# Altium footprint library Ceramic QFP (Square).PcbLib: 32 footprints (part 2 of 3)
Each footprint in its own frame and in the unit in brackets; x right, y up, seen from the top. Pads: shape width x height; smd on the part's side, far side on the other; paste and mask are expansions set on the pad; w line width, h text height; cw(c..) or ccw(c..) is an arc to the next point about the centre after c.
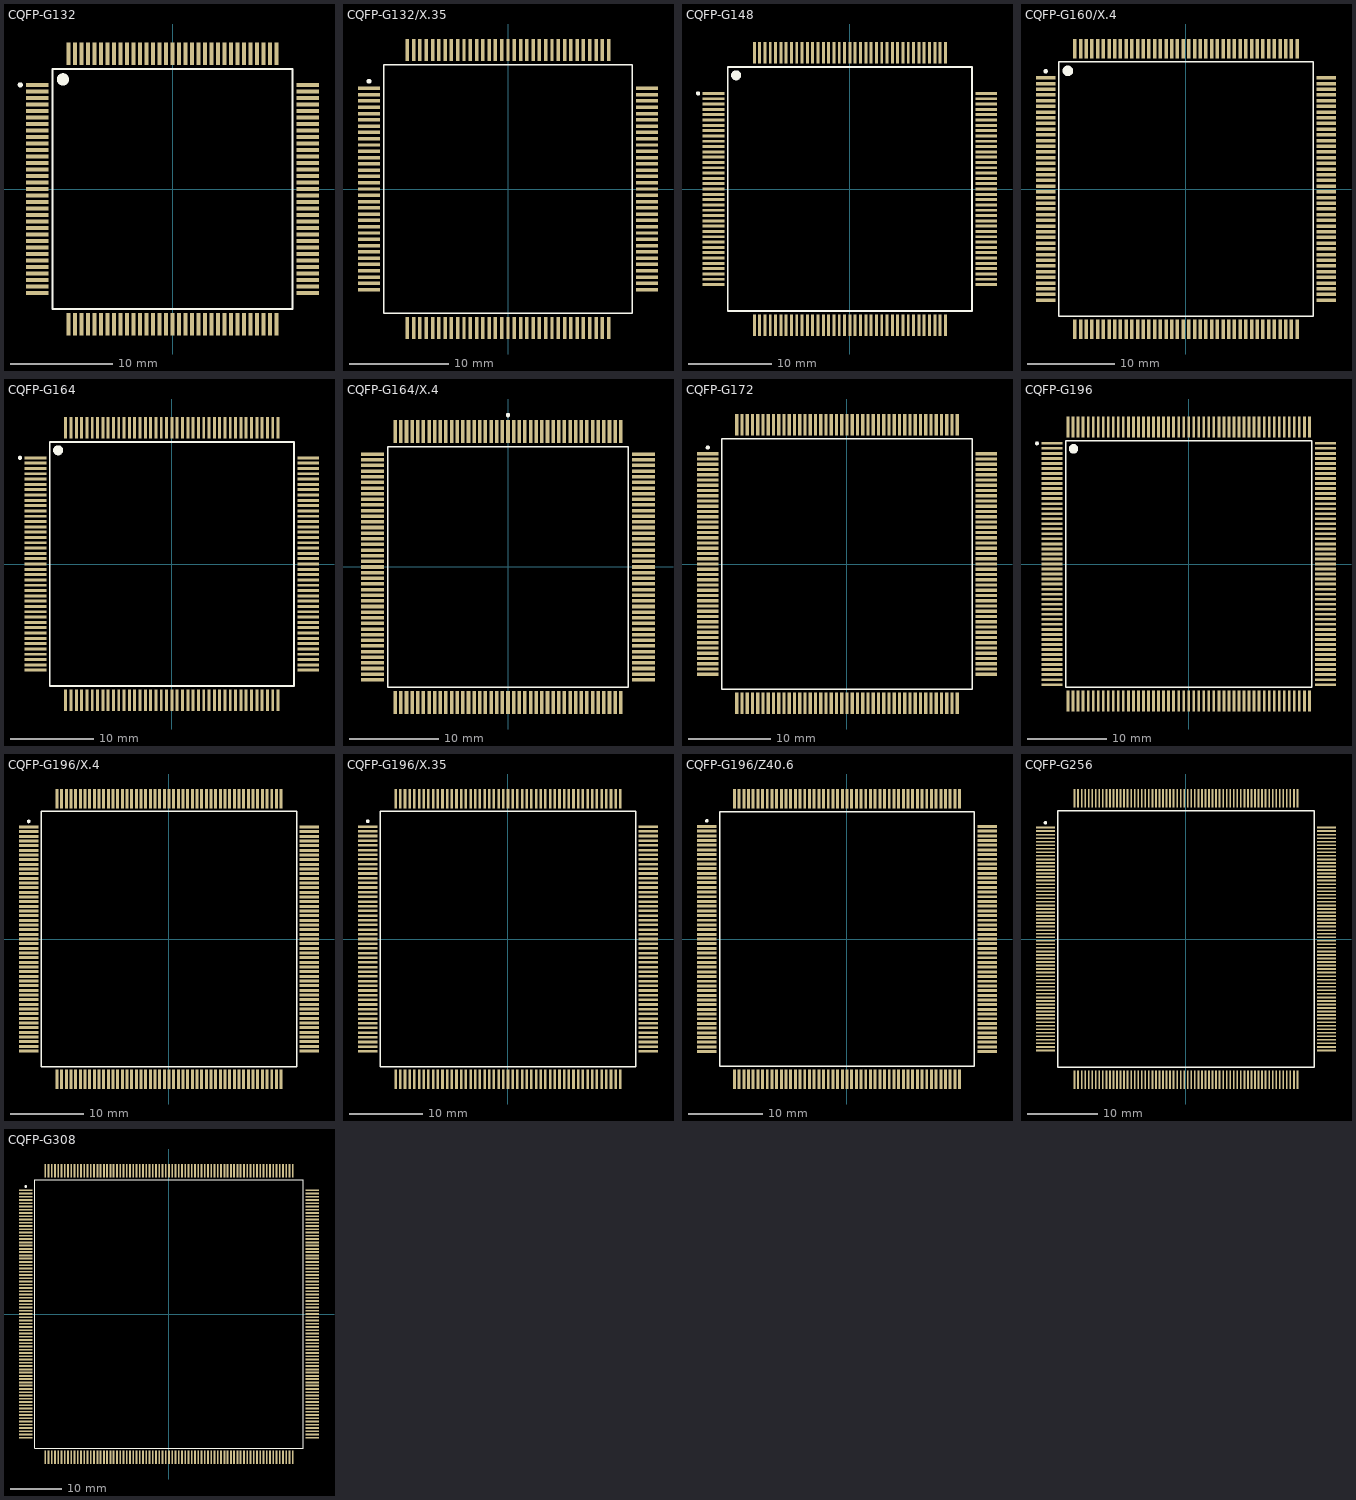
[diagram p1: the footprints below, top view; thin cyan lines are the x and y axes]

## CQFP-G132 [mm]
pads (132):
  rect 2.2x0.4 smd: 1(-13.2,10.16) 2(-13.2,9.525) 3(-13.2,8.89) 4(-13.2,8.255) 5(-13.2,7.62) 6(-13.2,6.985) 7(-13.2,6.35) 8(-13.2,5.715) 9(-13.2,5.08) 10(-13.2,4.445) 11(-13.2,3.81) 12(-13.2,3.175) 13(-13.2,2.54) 14(-13.2,1.905) 15(-13.2,1.27) 16(-13.2,0.635) 17(-13.2,0) 18(-13.2,-0.635) 19(-13.2,-1.27) 20(-13.2,-1.905) 21(-13.2,-2.54) 22(-13.2,-3.175) 23(-13.2,-3.81) 24(-13.2,-4.445) 25(-13.2,-5.08) 26(-13.2,-5.715) 27(-13.2,-6.35) 28(-13.2,-6.985) 29(-13.2,-7.62) 30(-13.2,-8.255) 31(-13.2,-8.89) 32(-13.2,-9.525) 33(-13.2,-10.16) 67(13.2,-10.16) 68(13.2,-9.525) 69(13.2,-8.89) 70(13.2,-8.255) 71(13.2,-7.62) 72(13.2,-6.985) 73(13.2,-6.35) 74(13.2,-5.715) 75(13.2,-5.08) 76(13.2,-4.445) 77(13.2,-3.81) 78(13.2,-3.175) 79(13.2,-2.54) 80(13.2,-1.905) 81(13.2,-1.27) 82(13.2,-0.635) 83(13.2,0) 84(13.2,0.635) 85(13.2,1.27) 86(13.2,1.905) 87(13.2,2.54) 88(13.2,3.175) 89(13.2,3.81) 90(13.2,4.445) 91(13.2,5.08) 92(13.2,5.715) 93(13.2,6.35) 94(13.2,6.985) 95(13.2,7.62) 96(13.2,8.255) 97(13.2,8.89) 98(13.2,9.525) 99(13.2,10.16)
  rect 0.4x2.2 smd: 34(-10.16,-13.2) 35(-9.525,-13.2) 36(-8.89,-13.2) 37(-8.255,-13.2) 38(-7.62,-13.2) 39(-6.985,-13.2) 40(-6.35,-13.2) 41(-5.715,-13.2) 42(-5.08,-13.2) 43(-4.445,-13.2) 44(-3.81,-13.2) 45(-3.175,-13.2) 46(-2.54,-13.2) 47(-1.905,-13.2) 48(-1.27,-13.2) 49(-0.635,-13.2) 50(0,-13.2) 51(0.635,-13.2) 52(1.27,-13.2) 53(1.905,-13.2) 54(2.54,-13.2) 55(3.175,-13.2) 56(3.81,-13.2) 57(4.445,-13.2) 58(5.08,-13.2) 59(5.715,-13.2) 60(6.35,-13.2) 61(6.985,-13.2) 62(7.62,-13.2) 63(8.255,-13.2) 64(8.89,-13.2) 65(9.525,-13.2) 66(10.16,-13.2) 100(10.16,13.2) 101(9.525,13.2) 102(8.89,13.2) 103(8.255,13.2) 104(7.62,13.2) 105(6.985,13.2) 106(6.35,13.2) 107(5.715,13.2) 108(5.08,13.2) 109(4.445,13.2) 110(3.81,13.2) 111(3.175,13.2) 112(2.54,13.2) 113(1.905,13.2) 114(1.27,13.2) 115(0.635,13.2) 116(0,13.2) 117(-0.635,13.2) 118(-1.27,13.2) 119(-1.905,13.2) 120(-2.54,13.2) 121(-3.175,13.2) 122(-3.81,13.2) 123(-4.445,13.2) 124(-5.08,13.2) 125(-5.715,13.2) 126(-6.35,13.2) 127(-6.985,13.2) 128(-7.62,13.2) 129(-8.255,13.2) 130(-8.89,13.2) 131(-9.525,13.2) 132(-10.16,13.2)
Top Overlay:
  circle w0.6: c-10.7,10.7 r0.3
  circle w0.25: c-14.86,10.16 r0.125
  lines w0.2: -11.7,-11.7 -11.7,11.7 11.7,11.7 11.7,-11.7 -11.7,-11.7

## CQFP-G132/X.35 [mm]
pads (132):
  rect 2.2x0.35 smd: 1(-14.05,10.16) 2(-14.05,9.525) 3(-14.05,8.89) 4(-14.05,8.255) 5(-14.05,7.62) 6(-14.05,6.985) 7(-14.05,6.35) 8(-14.05,5.715) 9(-14.05,5.08) 10(-14.05,4.445) 11(-14.05,3.81) 12(-14.05,3.175) 13(-14.05,2.54) 14(-14.05,1.905) 15(-14.05,1.27) 16(-14.05,0.635) 17(-14.05,0) 18(-14.05,-0.635) 19(-14.05,-1.27) 20(-14.05,-1.905) 21(-14.05,-2.54) 22(-14.05,-3.175) 23(-14.05,-3.81) 24(-14.05,-4.445) 25(-14.05,-5.08) 26(-14.05,-5.715) 27(-14.05,-6.35) 28(-14.05,-6.985) 29(-14.05,-7.62) 30(-14.05,-8.255) 31(-14.05,-8.89) 32(-14.05,-9.525) 33(-14.05,-10.16) 67(14.05,-10.16) 68(14.05,-9.525) 69(14.05,-8.89) 70(14.05,-8.255) 71(14.05,-7.62) 72(14.05,-6.985) 73(14.05,-6.35) 74(14.05,-5.715) 75(14.05,-5.08) 76(14.05,-4.445) 77(14.05,-3.81) 78(14.05,-3.175) 79(14.05,-2.54) 80(14.05,-1.905) 81(14.05,-1.27) 82(14.05,-0.635) 83(14.05,0) 84(14.05,0.635) 85(14.05,1.27) 86(14.05,1.905) 87(14.05,2.54) 88(14.05,3.175) 89(14.05,3.81) 90(14.05,4.445) 91(14.05,5.08) 92(14.05,5.715) 93(14.05,6.35) 94(14.05,6.985) 95(14.05,7.62) 96(14.05,8.255) 97(14.05,8.89) 98(14.05,9.525) 99(14.05,10.16)
  rect 0.35x2.2 smd: 34(-10.16,-14.05) 35(-9.525,-14.05) 36(-8.89,-14.05) 37(-8.255,-14.05) 38(-7.62,-14.05) 39(-6.985,-14.05) 40(-6.35,-14.05) 41(-5.715,-14.05) 42(-5.08,-14.05) 43(-4.445,-14.05) 44(-3.81,-14.05) 45(-3.175,-14.05) 46(-2.54,-14.05) 47(-1.905,-14.05) 48(-1.27,-14.05) 49(-0.635,-14.05) 50(0,-14.05) 51(0.635,-14.05) 52(1.27,-14.05) 53(1.905,-14.05) 54(2.54,-14.05) 55(3.175,-14.05) 56(3.81,-14.05) 57(4.445,-14.05) 58(5.08,-14.05) 59(5.715,-14.05) 60(6.35,-14.05) 61(6.985,-14.05) 62(7.62,-14.05) 63(8.255,-14.05) 64(8.89,-14.05) 65(9.525,-14.05) 66(10.16,-14.05) 100(10.16,14.05) 101(9.525,14.05) 102(8.89,14.05) 103(8.255,14.05) 104(7.62,14.05) 105(6.985,14.05) 106(6.35,14.05) 107(5.715,14.05) 108(5.08,14.05) 109(4.445,14.05) 110(3.81,14.05) 111(3.175,14.05) 112(2.54,14.05) 113(1.905,14.05) 114(1.27,14.05) 115(0.635,14.05) 116(0,14.05) 117(-0.635,14.05) 118(-1.27,14.05) 119(-1.905,14.05) 120(-2.54,14.05) 121(-3.175,14.05) 122(-3.81,14.05) 123(-4.445,14.05) 124(-5.08,14.05) 125(-5.715,14.05) 126(-6.35,14.05) 127(-6.985,14.05) 128(-7.62,14.05) 129(-8.255,14.05) 130(-8.89,14.05) 131(-9.525,14.05) 132(-10.16,14.05)
Top Overlay:
  circle w0.25: c-14.05,10.885 r0.125
  lines w0.2: -12.55,-12.55 12.55,-12.55 12.55,12.55 -12.55,12.55 -12.55,-12.55

## CQFP-G148 [mm]
pads (148):
  rect 2.6x0.35 smd: 1(-16.3,11.43) 2(-16.3,10.795) 3(-16.3,10.16) 4(-16.3,9.525) 5(-16.3,8.89) 6(-16.3,8.255) 7(-16.3,7.62) 8(-16.3,6.985) 9(-16.3,6.35) 10(-16.3,5.715) 11(-16.3,5.08) 12(-16.3,4.445) 13(-16.3,3.81) 14(-16.3,3.175) 15(-16.3,2.54) 16(-16.3,1.905) 17(-16.3,1.27) 18(-16.3,0.635) 19(-16.3,0) 20(-16.3,-0.635) 21(-16.3,-1.27) 22(-16.3,-1.905) 23(-16.3,-2.54) 24(-16.3,-3.175) 25(-16.3,-3.81) 26(-16.3,-4.445) 27(-16.3,-5.08) 28(-16.3,-5.715) 29(-16.3,-6.35) 30(-16.3,-6.985) 31(-16.3,-7.62) 32(-16.3,-8.255) 33(-16.3,-8.89) 34(-16.3,-9.525) 35(-16.3,-10.16) 36(-16.3,-10.795) 37(-16.3,-11.43) 75(16.3,-11.43) 76(16.3,-10.795) 77(16.3,-10.16) 78(16.3,-9.525) 79(16.3,-8.89) 80(16.3,-8.255) 81(16.3,-7.62) 82(16.3,-6.985) 83(16.3,-6.35) 84(16.3,-5.715) 85(16.3,-5.08) 86(16.3,-4.445) 87(16.3,-3.81) 88(16.3,-3.175) 89(16.3,-2.54) 90(16.3,-1.905) 91(16.3,-1.27) 92(16.3,-0.635) 93(16.3,0) 94(16.3,0.635) 95(16.3,1.27) 96(16.3,1.905) 97(16.3,2.54) 98(16.3,3.175) 99(16.3,3.81) 100(16.3,4.445) 101(16.3,5.08) 102(16.3,5.715) 103(16.3,6.35) 104(16.3,6.985) 105(16.3,7.62) 106(16.3,8.255) 107(16.3,8.89) 108(16.3,9.525) 109(16.3,10.16) 110(16.3,10.795) 111(16.3,11.43)
  rect 0.35x2.6 smd: 38(-11.43,-16.3) 39(-10.795,-16.3) 40(-10.16,-16.3) 41(-9.525,-16.3) 42(-8.89,-16.3) 43(-8.255,-16.3) 44(-7.62,-16.3) 45(-6.985,-16.3) 46(-6.35,-16.3) 47(-5.715,-16.3) 48(-5.08,-16.3) 49(-4.445,-16.3) 50(-3.81,-16.3) 51(-3.175,-16.3) 52(-2.54,-16.3) 53(-1.905,-16.3) 54(-1.27,-16.3) 55(-0.635,-16.3) 56(0,-16.3) 57(0.635,-16.3) 58(1.27,-16.3) 59(1.905,-16.3) 60(2.54,-16.3) 61(3.175,-16.3) 62(3.81,-16.3) 63(4.445,-16.3) 64(5.08,-16.3) 65(5.715,-16.3) 66(6.35,-16.3) 67(6.985,-16.3) 68(7.62,-16.3) 69(8.255,-16.3) 70(8.89,-16.3) 71(9.525,-16.3) 72(10.16,-16.3) 73(10.795,-16.3) 74(11.43,-16.3) 112(11.43,16.3) 113(10.795,16.3) 114(10.16,16.3) 115(9.525,16.3) 116(8.89,16.3) 117(8.255,16.3) 118(7.62,16.3) 119(6.985,16.3) 120(6.35,16.3) 121(5.715,16.3) 122(5.08,16.3) 123(4.445,16.3) 124(3.81,16.3) 125(3.175,16.3) 126(2.54,16.3) 127(1.905,16.3) 128(1.27,16.3) 129(0.635,16.3) 130(0,16.3) 131(-0.635,16.3) 132(-1.27,16.3) 133(-1.905,16.3) 134(-2.54,16.3) 135(-3.175,16.3) 136(-3.81,16.3) 137(-4.445,16.3) 138(-5.08,16.3) 139(-5.715,16.3) 140(-6.35,16.3) 141(-6.985,16.3) 142(-7.62,16.3) 143(-8.255,16.3) 144(-8.89,16.3) 145(-9.525,16.3) 146(-10.16,16.3) 147(-10.795,16.3) 148(-11.43,16.3)
Top Overlay:
  circle w0.6: c-13.6,13.6 r0.3
  circle w0.25: c-18.16,11.43 r0.125
  lines w0.2: -14.6,-14.6 -14.6,14.6 14.6,14.6 14.6,-14.6 -14.6,-14.6

## CQFP-G160/X.4 [mm]
pads (160):
  rect 2.2x0.4 smd: 1(-16,12.675) 2(-16,12.025) 3(-16,11.375) 4(-16,10.725) 5(-16,10.075) 6(-16,9.425) 7(-16,8.775) 8(-16,8.125) 9(-16,7.475) 10(-16,6.825) 11(-16,6.175) 12(-16,5.525) 13(-16,4.875) 14(-16,4.225) 15(-16,3.575) 16(-16,2.925) 17(-16,2.275) 18(-16,1.625) 19(-16,0.975) 20(-16,0.325) 21(-16,-0.325) 22(-16,-0.975) 23(-16,-1.625) 24(-16,-2.275) 25(-16,-2.925) 26(-16,-3.575) 27(-16,-4.225) 28(-16,-4.875) 29(-16,-5.525) 30(-16,-6.175) 31(-16,-6.825) 32(-16,-7.475) 33(-16,-8.125) 34(-16,-8.775) 35(-16,-9.425) 36(-16,-10.075) 37(-16,-10.725) 38(-16,-11.375) 39(-16,-12.025) 40(-16,-12.675) 81(16,-12.675) 82(16,-12.025) 83(16,-11.375) 84(16,-10.725) 85(16,-10.075) 86(16,-9.425) 87(16,-8.775) 88(16,-8.125) 89(16,-7.475) 90(16,-6.825) 91(16,-6.175) 92(16,-5.525) 93(16,-4.875) 94(16,-4.225) 95(16,-3.575) 96(16,-2.925) 97(16,-2.275) 98(16,-1.625) 99(16,-0.975) 100(16,-0.325) 101(16,0.325) 102(16,0.975) 103(16,1.625) 104(16,2.275) 105(16,2.925) 106(16,3.575) 107(16,4.225) 108(16,4.875) 109(16,5.525) 110(16,6.175) 111(16,6.825) 112(16,7.475) 113(16,8.125) 114(16,8.775) 115(16,9.425) 116(16,10.075) 117(16,10.725) 118(16,11.375) 119(16,12.025) 120(16,12.675)
  rect 0.4x2.2 smd: 41(-12.675,-16) 42(-12.025,-16) 43(-11.375,-16) 44(-10.725,-16) 45(-10.075,-16) 46(-9.425,-16) 47(-8.775,-16) 48(-8.125,-16) 49(-7.475,-16) 50(-6.825,-16) 51(-6.175,-16) 52(-5.525,-16) 53(-4.875,-16) 54(-4.225,-16) 55(-3.575,-16) 56(-2.925,-16) 57(-2.275,-16) 58(-1.625,-16) 59(-0.975,-16) 60(-0.325,-16) 61(0.325,-16) 62(0.975,-16) 63(1.625,-16) 64(2.275,-16) 65(2.925,-16) 66(3.575,-16) 67(4.225,-16) 68(4.875,-16) 69(5.525,-16) 70(6.175,-16) 71(6.825,-16) 72(7.475,-16) 73(8.125,-16) 74(8.775,-16) 75(9.425,-16) 76(10.075,-16) 77(10.725,-16) 78(11.375,-16) 79(12.025,-16) 80(12.675,-16) 121(12.675,16) 122(12.025,16) 123(11.375,16) 124(10.725,16) 125(10.075,16) 126(9.425,16) 127(8.775,16) 128(8.125,16) 129(7.475,16) 130(6.825,16) 131(6.175,16) 132(5.525,16) 133(4.875,16) 134(4.225,16) 135(3.575,16) 136(2.925,16) 137(2.275,16) 138(1.625,16) 139(0.975,16) 140(0.325,16) 141(-0.325,16) 142(-0.975,16) 143(-1.625,16) 144(-2.275,16) 145(-2.925,16) 146(-3.575,16) 147(-4.225,16) 148(-4.875,16) 149(-5.525,16) 150(-6.175,16) 151(-6.825,16) 152(-7.475,16) 153(-8.125,16) 154(-8.775,16) 155(-9.425,16) 156(-10.075,16) 157(-10.725,16) 158(-11.375,16) 159(-12.025,16) 160(-12.675,16)
Top Overlay:
  circle w0.6: c-13.47,13.47 r0.3
  circle w0.25: c-16,13.425 r0.125
  lines w0.2: -14.5,-14.5 -14.5,14.5 14.5,14.5 14.5,-14.5 -14.5,-14.5

## CQFP-G164 [mm]
pads (164):
  rect 2.6x0.35 smd: 1(-16.3,12.7) 2(-16.3,12.065) 3(-16.3,11.43) 4(-16.3,10.795) 5(-16.3,10.16) 6(-16.3,9.525) 7(-16.3,8.89) 8(-16.3,8.255) 9(-16.3,7.62) 10(-16.3,6.985) 11(-16.3,6.35) 12(-16.3,5.715) 13(-16.3,5.08) 14(-16.3,4.445) 15(-16.3,3.81) 16(-16.3,3.175) 17(-16.3,2.54) 18(-16.3,1.905) 19(-16.3,1.27) 20(-16.3,0.635) 21(-16.3,0) 22(-16.3,-0.635) 23(-16.3,-1.27) 24(-16.3,-1.905) 25(-16.3,-2.54) 26(-16.3,-3.175) 27(-16.3,-3.81) 28(-16.3,-4.445) 29(-16.3,-5.08) 30(-16.3,-5.715) 31(-16.3,-6.35) 32(-16.3,-6.985) 33(-16.3,-7.62) 34(-16.3,-8.255) 35(-16.3,-8.89) 36(-16.3,-9.525) 37(-16.3,-10.16) 38(-16.3,-10.795) 39(-16.3,-11.43) 40(-16.3,-12.065) 41(-16.3,-12.7) 83(16.3,-12.7) 84(16.3,-12.065) 85(16.3,-11.43) 86(16.3,-10.795) 87(16.3,-10.16) 88(16.3,-9.525) 89(16.3,-8.89) 90(16.3,-8.255) 91(16.3,-7.62) 92(16.3,-6.985) 93(16.3,-6.35) 94(16.3,-5.715) 95(16.3,-5.08) 96(16.3,-4.445) 97(16.3,-3.81) 98(16.3,-3.175) 99(16.3,-2.54) 100(16.3,-1.905) 101(16.3,-1.27) 102(16.3,-0.635) 103(16.3,0) 104(16.3,0.635) 105(16.3,1.27) 106(16.3,1.905) 107(16.3,2.54) 108(16.3,3.175) 109(16.3,3.81) 110(16.3,4.445) 111(16.3,5.08) 112(16.3,5.715) 113(16.3,6.35) 114(16.3,6.985) 115(16.3,7.62) 116(16.3,8.255) 117(16.3,8.89) 118(16.3,9.525) 119(16.3,10.16) 120(16.3,10.795) 121(16.3,11.43) 122(16.3,12.065) 123(16.3,12.7)
  rect 0.35x2.6 smd: 42(-12.7,-16.3) 43(-12.065,-16.3) 44(-11.43,-16.3) 45(-10.795,-16.3) 46(-10.16,-16.3) 47(-9.525,-16.3) 48(-8.89,-16.3) 49(-8.255,-16.3) 50(-7.62,-16.3) 51(-6.985,-16.3) 52(-6.35,-16.3) 53(-5.715,-16.3) 54(-5.08,-16.3) 55(-4.445,-16.3) 56(-3.81,-16.3) 57(-3.175,-16.3) 58(-2.54,-16.3) 59(-1.905,-16.3) 60(-1.27,-16.3) 61(-0.635,-16.3) 62(0,-16.3) 63(0.635,-16.3) 64(1.27,-16.3) 65(1.905,-16.3) 66(2.54,-16.3) 67(3.175,-16.3) 68(3.81,-16.3) 69(4.445,-16.3) 70(5.08,-16.3) 71(5.715,-16.3) 72(6.35,-16.3) 73(6.985,-16.3) 74(7.62,-16.3) 75(8.255,-16.3) 76(8.89,-16.3) 77(9.525,-16.3) 78(10.16,-16.3) 79(10.795,-16.3) 80(11.43,-16.3) 81(12.065,-16.3) 82(12.7,-16.3) 124(12.7,16.3) 125(12.065,16.3) 126(11.43,16.3) 127(10.795,16.3) 128(10.16,16.3) 129(9.525,16.3) 130(8.89,16.3) 131(8.255,16.3) 132(7.62,16.3) 133(6.985,16.3) 134(6.35,16.3) 135(5.715,16.3) 136(5.08,16.3) 137(4.445,16.3) 138(3.81,16.3) 139(3.175,16.3) 140(2.54,16.3) 141(1.905,16.3) 142(1.27,16.3) 143(0.635,16.3) 144(0,16.3) 145(-0.635,16.3) 146(-1.27,16.3) 147(-1.905,16.3) 148(-2.54,16.3) 149(-3.175,16.3) 150(-3.81,16.3) 151(-4.445,16.3) 152(-5.08,16.3) 153(-5.715,16.3) 154(-6.35,16.3) 155(-6.985,16.3) 156(-7.62,16.3) 157(-8.255,16.3) 158(-8.89,16.3) 159(-9.525,16.3) 160(-10.16,16.3) 161(-10.795,16.3) 162(-11.43,16.3) 163(-12.065,16.3) 164(-12.7,16.3)
Top Overlay:
  circle w0.25: c-18.16,12.7 r0.125
  circle w0.6: c-13.6,13.6 r0.3
  lines w0.2: -14.6,-14.6 14.6,-14.6 14.6,14.6 -14.6,14.6 -14.6,-14.6

## CQFP-G164/X.4 [mm]
pads (164):
  rect 0.4x2.6 smd: 1(0,15.25) 2(-0.635,15.25) 3(-1.27,15.25) 4(-1.905,15.25) 5(-2.54,15.25) 6(-3.175,15.25) 7(-3.81,15.25) 8(-4.445,15.25) 9(-5.08,15.25) 10(-5.715,15.25) 11(-6.35,15.25) 12(-6.985,15.25) 13(-7.62,15.25) 14(-8.255,15.25) 15(-8.89,15.25) 16(-9.525,15.25) 17(-10.16,15.25) 18(-10.795,15.25) 19(-11.43,15.25) 20(-12.065,15.25) 21(-12.7,15.25) 63(-12.7,-15.25) 64(-12.065,-15.25) 65(-11.43,-15.25) 66(-10.795,-15.25) 67(-10.16,-15.25) 68(-9.525,-15.25) 69(-8.89,-15.25) 70(-8.255,-15.25) 71(-7.62,-15.25) 72(-6.985,-15.25) 73(-6.35,-15.25) 74(-5.715,-15.25) 75(-5.08,-15.25) 76(-4.445,-15.25) 77(-3.81,-15.25) 78(-3.175,-15.25) 79(-2.54,-15.25) 80(-1.905,-15.25) 81(-1.27,-15.25) 82(-0.635,-15.25) 83(0,-15.25) 84(0.635,-15.25) 85(1.27,-15.25) 86(1.905,-15.25) 87(2.54,-15.25) 88(3.175,-15.25) 89(3.81,-15.25) 90(4.445,-15.25) 91(5.08,-15.25) 92(5.715,-15.25) 93(6.35,-15.25) 94(6.985,-15.25) 95(7.62,-15.25) 96(8.255,-15.25) 97(8.89,-15.25) 98(9.525,-15.25) 99(10.16,-15.25) 100(10.795,-15.25) 101(11.43,-15.25) 102(12.065,-15.25) 103(12.7,-15.25) 145(12.7,15.25) 146(12.065,15.25) 147(11.43,15.25) 148(10.795,15.25) 149(10.16,15.25) 150(9.525,15.25) 151(8.89,15.25) 152(8.255,15.25) 153(7.62,15.25) 154(6.985,15.25) 155(6.35,15.25) 156(5.715,15.25) 157(5.08,15.25) 158(4.445,15.25) 159(3.81,15.25) 160(3.175,15.25) 161(2.54,15.25) 162(1.905,15.25) 163(1.27,15.25) 164(0.635,15.25)
  rect 2.6x0.4 smd: 22(-15.25,12.7) 23(-15.25,12.065) 24(-15.25,11.43) 25(-15.25,10.795) 26(-15.25,10.16) 27(-15.25,9.525) 28(-15.25,8.89) 29(-15.25,8.255) 30(-15.25,7.62) 31(-15.25,6.985) 32(-15.25,6.35) 33(-15.25,5.715) 34(-15.25,5.08) 35(-15.25,4.445) 36(-15.25,3.81) 37(-15.25,3.175) 38(-15.25,2.54) 39(-15.25,1.905) 40(-15.25,1.27) 41(-15.25,0.635) 42(-15.25,0) 43(-15.25,-0.635) 44(-15.25,-1.27) 45(-15.25,-1.905) 46(-15.25,-2.54) 47(-15.25,-3.175) 48(-15.25,-3.81) 49(-15.25,-4.445) 50(-15.25,-5.08) 51(-15.25,-5.715) 52(-15.25,-6.35) 53(-15.25,-6.985) 54(-15.25,-7.62) 55(-15.25,-8.255) 56(-15.25,-8.89) 57(-15.25,-9.525) 58(-15.25,-10.16) 59(-15.25,-10.795) 60(-15.25,-11.43) 61(-15.25,-12.065) 62(-15.25,-12.7) 104(15.25,-12.7) 105(15.25,-12.065) 106(15.25,-11.43) 107(15.25,-10.795) 108(15.25,-10.16) 109(15.25,-9.525) 110(15.25,-8.89) 111(15.25,-8.255) 112(15.25,-7.62) 113(15.25,-6.985) 114(15.25,-6.35) 115(15.25,-5.715) 116(15.25,-5.08) 117(15.25,-4.445) 118(15.25,-3.81) 119(15.25,-3.175) 120(15.25,-2.54) 121(15.25,-1.905) 122(15.25,-1.27) 123(15.25,-0.635) 124(15.25,0) 125(15.25,0.635) 126(15.25,1.27) 127(15.25,1.905) 128(15.25,2.54) 129(15.25,3.175) 130(15.25,3.81) 131(15.25,4.445) 132(15.25,5.08) 133(15.25,5.715) 134(15.25,6.35) 135(15.25,6.985) 136(15.25,7.62) 137(15.25,8.255) 138(15.25,8.89) 139(15.25,9.525) 140(15.25,10.16) 141(15.25,10.795) 142(15.25,11.43) 143(15.25,12.065) 144(15.25,12.7)
Top Overlay:
  circle w0.25: c0,17.1 r0.125
  lines w0.2: -13.55,-13.55 -13.55,13.55 13.55,13.55 13.55,-13.55 -13.55,-13.55

## CQFP-G172 [mm]
pads (172):
  rect 2.6x0.4 smd: 1(-16.85,13.335) 2(-16.85,12.7) 3(-16.85,12.065) 4(-16.85,11.43) 5(-16.85,10.795) 6(-16.85,10.16) 7(-16.85,9.525) 8(-16.85,8.89) 9(-16.85,8.255) 10(-16.85,7.62) 11(-16.85,6.985) 12(-16.85,6.35) 13(-16.85,5.715) 14(-16.85,5.08) 15(-16.85,4.445) 16(-16.85,3.81) 17(-16.85,3.175) 18(-16.85,2.54) 19(-16.85,1.905) 20(-16.85,1.27) 21(-16.85,0.635) 22(-16.85,0) 23(-16.85,-0.635) 24(-16.85,-1.27) 25(-16.85,-1.905) 26(-16.85,-2.54) 27(-16.85,-3.175) 28(-16.85,-3.81) 29(-16.85,-4.445) 30(-16.85,-5.08) 31(-16.85,-5.715) 32(-16.85,-6.35) 33(-16.85,-6.985) 34(-16.85,-7.62) 35(-16.85,-8.255) 36(-16.85,-8.89) 37(-16.85,-9.525) 38(-16.85,-10.16) 39(-16.85,-10.795) 40(-16.85,-11.43) 41(-16.85,-12.065) 42(-16.85,-12.7) 43(-16.85,-13.335) 87(16.85,-13.335) 88(16.85,-12.7) 89(16.85,-12.065) 90(16.85,-11.43) 91(16.85,-10.795) 92(16.85,-10.16) 93(16.85,-9.525) 94(16.85,-8.89) 95(16.85,-8.255) 96(16.85,-7.62) 97(16.85,-6.985) 98(16.85,-6.35) 99(16.85,-5.715) 100(16.85,-5.08) 101(16.85,-4.445) 102(16.85,-3.81) 103(16.85,-3.175) 104(16.85,-2.54) 105(16.85,-1.905) 106(16.85,-1.27) 107(16.85,-0.635) 108(16.85,0) 109(16.85,0.635) 110(16.85,1.27) 111(16.85,1.905) 112(16.85,2.54) 113(16.85,3.175) 114(16.85,3.81) 115(16.85,4.445) 116(16.85,5.08) 117(16.85,5.715) 118(16.85,6.35) 119(16.85,6.985) 120(16.85,7.62) 121(16.85,8.255) 122(16.85,8.89) 123(16.85,9.525) 124(16.85,10.16) 125(16.85,10.795) 126(16.85,11.43) 127(16.85,12.065) 128(16.85,12.7) 129(16.85,13.335)
  rect 0.4x2.6 smd: 44(-13.335,-16.85) 45(-12.7,-16.85) 46(-12.065,-16.85) 47(-11.43,-16.85) 48(-10.795,-16.85) 49(-10.16,-16.85) 50(-9.525,-16.85) 51(-8.89,-16.85) 52(-8.255,-16.85) 53(-7.62,-16.85) 54(-6.985,-16.85) 55(-6.35,-16.85) 56(-5.715,-16.85) 57(-5.08,-16.85) 58(-4.445,-16.85) 59(-3.81,-16.85) 60(-3.175,-16.85) 61(-2.54,-16.85) 62(-1.905,-16.85) 63(-1.27,-16.85) 64(-0.635,-16.85) 65(0,-16.85) 66(0.635,-16.85) 67(1.27,-16.85) 68(1.905,-16.85) 69(2.54,-16.85) 70(3.175,-16.85) 71(3.81,-16.85) 72(4.445,-16.85) 73(5.08,-16.85) 74(5.715,-16.85) 75(6.35,-16.85) 76(6.985,-16.85) 77(7.62,-16.85) 78(8.255,-16.85) 79(8.89,-16.85) 80(9.525,-16.85) 81(10.16,-16.85) 82(10.795,-16.85) 83(11.43,-16.85) 84(12.065,-16.85) 85(12.7,-16.85) 86(13.335,-16.85) 130(13.335,16.85) 131(12.7,16.85) 132(12.065,16.85) 133(11.43,16.85) 134(10.795,16.85) 135(10.16,16.85) 136(9.525,16.85) 137(8.89,16.85) 138(8.255,16.85) 139(7.62,16.85) 140(6.985,16.85) 141(6.35,16.85) 142(5.715,16.85) 143(5.08,16.85) 144(4.445,16.85) 145(3.81,16.85) 146(3.175,16.85) 147(2.54,16.85) 148(1.905,16.85) 149(1.27,16.85) 150(0.635,16.85) 151(0,16.85) 152(-0.635,16.85) 153(-1.27,16.85) 154(-1.905,16.85) 155(-2.54,16.85) 156(-3.175,16.85) 157(-3.81,16.85) 158(-4.445,16.85) 159(-5.08,16.85) 160(-5.715,16.85) 161(-6.35,16.85) 162(-6.985,16.85) 163(-7.62,16.85) 164(-8.255,16.85) 165(-8.89,16.85) 166(-9.525,16.85) 167(-10.16,16.85) 168(-10.795,16.85) 169(-11.43,16.85) 170(-12.065,16.85) 171(-12.7,16.85) 172(-13.335,16.85)
Top Overlay:
  circle w0.25: c-16.85,14.085 r0.125
  lines w0.2: -15.15,-15.15 15.15,-15.15 15.15,15.15 -15.15,15.15 -15.15,-15.15

## CQFP-G196 [mm]
pads (196):
  rect 2.65x0.35 smd: 1(-17.275,15.24) 2(-17.275,14.605) 3(-17.275,13.97) 4(-17.275,13.335) 5(-17.275,12.7) 6(-17.275,12.065) 7(-17.275,11.43) 8(-17.275,10.795) 9(-17.275,10.16) 10(-17.275,9.525) 11(-17.275,8.89) 12(-17.275,8.255) 13(-17.275,7.62) 14(-17.275,6.985) 15(-17.275,6.35) 16(-17.275,5.715) 17(-17.275,5.08) 18(-17.275,4.445) 19(-17.275,3.81) 20(-17.275,3.175) 21(-17.275,2.54) 22(-17.275,1.905) 23(-17.275,1.27) 24(-17.275,0.635) 25(-17.275,0) 26(-17.275,-0.635) 27(-17.275,-1.27) 28(-17.275,-1.905) 29(-17.275,-2.54) 30(-17.275,-3.175) 31(-17.275,-3.81) 32(-17.275,-4.445) 33(-17.275,-5.08) 34(-17.275,-5.715) 35(-17.275,-6.35) 36(-17.275,-6.985) 37(-17.275,-7.62) 38(-17.275,-8.255) 39(-17.275,-8.89) 40(-17.275,-9.525) 41(-17.275,-10.16) 42(-17.275,-10.795) 43(-17.275,-11.43) 44(-17.275,-12.065) 45(-17.275,-12.7) 46(-17.275,-13.335) 47(-17.275,-13.97) 48(-17.275,-14.605) 49(-17.275,-15.24) 99(17.275,-15.24) 100(17.275,-14.605) 101(17.275,-13.97) 102(17.275,-13.335) 103(17.275,-12.7) 104(17.275,-12.065) 105(17.275,-11.43) 106(17.275,-10.795) 107(17.275,-10.16) 108(17.275,-9.525) 109(17.275,-8.89) 110(17.275,-8.255) 111(17.275,-7.62) 112(17.275,-6.985) 113(17.275,-6.35) 114(17.275,-5.715) 115(17.275,-5.08) 116(17.275,-4.445) 117(17.275,-3.81) 118(17.275,-3.175) 119(17.275,-2.54) 120(17.275,-1.905) 121(17.275,-1.27) 122(17.275,-0.635) 123(17.275,0) 124(17.275,0.635) 125(17.275,1.27) 126(17.275,1.905) 127(17.275,2.54) 128(17.275,3.175) 129(17.275,3.81) 130(17.275,4.445) 131(17.275,5.08) 132(17.275,5.715) 133(17.275,6.35) 134(17.275,6.985) 135(17.275,7.62) 136(17.275,8.255) 137(17.275,8.89) 138(17.275,9.525) 139(17.275,10.16) 140(17.275,10.795) 141(17.275,11.43) 142(17.275,12.065) 143(17.275,12.7) 144(17.275,13.335) 145(17.275,13.97) 146(17.275,14.605) 147(17.275,15.24)
  rect 0.35x2.65 smd: 50(-15.24,-17.275) 51(-14.605,-17.275) 52(-13.97,-17.275) 53(-13.335,-17.275) 54(-12.7,-17.275) 55(-12.065,-17.275) 56(-11.43,-17.275) 57(-10.795,-17.275) 58(-10.16,-17.275) 59(-9.525,-17.275) 60(-8.89,-17.275) 61(-8.255,-17.275) 62(-7.62,-17.275) 63(-6.985,-17.275) 64(-6.35,-17.275) 65(-5.715,-17.275) 66(-5.08,-17.275) 67(-4.445,-17.275) 68(-3.81,-17.275) 69(-3.175,-17.275) 70(-2.54,-17.275) 71(-1.905,-17.275) 72(-1.27,-17.275) 73(-0.635,-17.275) 74(0,-17.275) 75(0.635,-17.275) 76(1.27,-17.275) 77(1.905,-17.275) 78(2.54,-17.275) 79(3.175,-17.275) 80(3.81,-17.275) 81(4.445,-17.275) 82(5.08,-17.275) 83(5.715,-17.275) 84(6.35,-17.275) 85(6.985,-17.275) 86(7.62,-17.275) 87(8.255,-17.275) 88(8.89,-17.275) 89(9.525,-17.275) 90(10.16,-17.275) 91(10.795,-17.275) 92(11.43,-17.275) 93(12.065,-17.275) 94(12.7,-17.275) 95(13.335,-17.275) 96(13.97,-17.275) 97(14.605,-17.275) 98(15.24,-17.275) 148(15.24,17.275) 149(14.605,17.275) 150(13.97,17.275) 151(13.335,17.275) 152(12.7,17.275) 153(12.065,17.275) 154(11.43,17.275) 155(10.795,17.275) 156(10.16,17.275) 157(9.525,17.275) 158(8.89,17.275) 159(8.255,17.275) 160(7.62,17.275) 161(6.985,17.275) 162(6.35,17.275) 163(5.715,17.275) 164(5.08,17.275) 165(4.445,17.275) 166(3.81,17.275) 167(3.175,17.275) 168(2.54,17.275) 169(1.905,17.275) 170(1.27,17.275) 171(0.635,17.275) 172(0,17.275) 173(-0.635,17.275) 174(-1.27,17.275) 175(-1.905,17.275) 176(-2.54,17.275) 177(-3.175,17.275) 178(-3.81,17.275) 179(-4.445,17.275) 180(-5.08,17.275) 181(-5.715,17.275) 182(-6.35,17.275) 183(-6.985,17.275) 184(-7.62,17.275) 185(-8.255,17.275) 186(-8.89,17.275) 187(-9.525,17.275) 188(-10.16,17.275) 189(-10.795,17.275) 190(-11.43,17.275) 191(-12.065,17.275) 192(-12.7,17.275) 193(-13.335,17.275) 194(-13.97,17.275) 195(-14.605,17.275) 196(-15.24,17.275)
Top Overlay:
  circle w0.25: c-19.16,15.24 r0.125
  circle w0.6: c-14.55,14.55 r0.3
  lines w0.2: -15.55,-15.55 15.55,-15.55 15.55,15.55 -15.55,15.55 -15.55,-15.55

## CQFP-G196/X.4 [mm]
pads (196):
  rect 2.65x0.4 smd: 1(-19.075,15.24) 2(-19.075,14.605) 3(-19.075,13.97) 4(-19.075,13.335) 5(-19.075,12.7) 6(-19.075,12.065) 7(-19.075,11.43) 8(-19.075,10.795) 9(-19.075,10.16) 10(-19.075,9.525) 11(-19.075,8.89) 12(-19.075,8.255) 13(-19.075,7.62) 14(-19.075,6.985) 15(-19.075,6.35) 16(-19.075,5.715) 17(-19.075,5.08) 18(-19.075,4.445) 19(-19.075,3.81) 20(-19.075,3.175) 21(-19.075,2.54) 22(-19.075,1.905) 23(-19.075,1.27) 24(-19.075,0.635) 25(-19.075,0) 26(-19.075,-0.635) 27(-19.075,-1.27) 28(-19.075,-1.905) 29(-19.075,-2.54) 30(-19.075,-3.175) 31(-19.075,-3.81) 32(-19.075,-4.445) 33(-19.075,-5.08) 34(-19.075,-5.715) 35(-19.075,-6.35) 36(-19.075,-6.985) 37(-19.075,-7.62) 38(-19.075,-8.255) 39(-19.075,-8.89) 40(-19.075,-9.525) 41(-19.075,-10.16) 42(-19.075,-10.795) 43(-19.075,-11.43) 44(-19.075,-12.065) 45(-19.075,-12.7) 46(-19.075,-13.335) 47(-19.075,-13.97) 48(-19.075,-14.605) 49(-19.075,-15.24) 99(19.075,-15.24) 100(19.075,-14.605) 101(19.075,-13.97) 102(19.075,-13.335) 103(19.075,-12.7) 104(19.075,-12.065) 105(19.075,-11.43) 106(19.075,-10.795) 107(19.075,-10.16) 108(19.075,-9.525) 109(19.075,-8.89) 110(19.075,-8.255) 111(19.075,-7.62) 112(19.075,-6.985) 113(19.075,-6.35) 114(19.075,-5.715) 115(19.075,-5.08) 116(19.075,-4.445) 117(19.075,-3.81) 118(19.075,-3.175) 119(19.075,-2.54) 120(19.075,-1.905) 121(19.075,-1.27) 122(19.075,-0.635) 123(19.075,0) 124(19.075,0.635) 125(19.075,1.27) 126(19.075,1.905) 127(19.075,2.54) 128(19.075,3.175) 129(19.075,3.81) 130(19.075,4.445) 131(19.075,5.08) 132(19.075,5.715) 133(19.075,6.35) 134(19.075,6.985) 135(19.075,7.62) 136(19.075,8.255) 137(19.075,8.89) 138(19.075,9.525) 139(19.075,10.16) 140(19.075,10.795) 141(19.075,11.43) 142(19.075,12.065) 143(19.075,12.7) 144(19.075,13.335) 145(19.075,13.97) 146(19.075,14.605) 147(19.075,15.24)
  rect 0.4x2.65 smd: 50(-15.24,-19.075) 51(-14.605,-19.075) 52(-13.97,-19.075) 53(-13.335,-19.075) 54(-12.7,-19.075) 55(-12.065,-19.075) 56(-11.43,-19.075) 57(-10.795,-19.075) 58(-10.16,-19.075) 59(-9.525,-19.075) 60(-8.89,-19.075) 61(-8.255,-19.075) 62(-7.62,-19.075) 63(-6.985,-19.075) 64(-6.35,-19.075) 65(-5.715,-19.075) 66(-5.08,-19.075) 67(-4.445,-19.075) 68(-3.81,-19.075) 69(-3.175,-19.075) 70(-2.54,-19.075) 71(-1.905,-19.075) 72(-1.27,-19.075) 73(-0.635,-19.075) 74(0,-19.075) 75(0.635,-19.075) 76(1.27,-19.075) 77(1.905,-19.075) 78(2.54,-19.075) 79(3.175,-19.075) 80(3.81,-19.075) 81(4.445,-19.075) 82(5.08,-19.075) 83(5.715,-19.075) 84(6.35,-19.075) 85(6.985,-19.075) 86(7.62,-19.075) 87(8.255,-19.075) 88(8.89,-19.075) 89(9.525,-19.075) 90(10.16,-19.075) 91(10.795,-19.075) 92(11.43,-19.075) 93(12.065,-19.075) 94(12.7,-19.075) 95(13.335,-19.075) 96(13.97,-19.075) 97(14.605,-19.075) 98(15.24,-19.075) 148(15.24,19.075) 149(14.605,19.075) 150(13.97,19.075) 151(13.335,19.075) 152(12.7,19.075) 153(12.065,19.075) 154(11.43,19.075) 155(10.795,19.075) 156(10.16,19.075) 157(9.525,19.075) 158(8.89,19.075) 159(8.255,19.075) 160(7.62,19.075) 161(6.985,19.075) 162(6.35,19.075) 163(5.715,19.075) 164(5.08,19.075) 165(4.445,19.075) 166(3.81,19.075) 167(3.175,19.075) 168(2.54,19.075) 169(1.905,19.075) 170(1.27,19.075) 171(0.635,19.075) 172(0,19.075) 173(-0.635,19.075) 174(-1.27,19.075) 175(-1.905,19.075) 176(-2.54,19.075) 177(-3.175,19.075) 178(-3.81,19.075) 179(-4.445,19.075) 180(-5.08,19.075) 181(-5.715,19.075) 182(-6.35,19.075) 183(-6.985,19.075) 184(-7.62,19.075) 185(-8.255,19.075) 186(-8.89,19.075) 187(-9.525,19.075) 188(-10.16,19.075) 189(-10.795,19.075) 190(-11.43,19.075) 191(-12.065,19.075) 192(-12.7,19.075) 193(-13.335,19.075) 194(-13.97,19.075) 195(-14.605,19.075) 196(-15.24,19.075)
Top Overlay:
  circle w0.25: c-19.075,15.99 r0.125
  lines w0.2: -17.35,-17.35 17.35,-17.35 17.35,17.35 -17.35,17.35 -17.35,-17.35

## CQFP-G196/X.35 [mm]
pads (196):
  rect 2.65x0.35 smd: 1(-19.025,15.24) 2(-19.025,14.605) 3(-19.025,13.97) 4(-19.025,13.335) 5(-19.025,12.7) 6(-19.025,12.065) 7(-19.025,11.43) 8(-19.025,10.795) 9(-19.025,10.16) 10(-19.025,9.525) 11(-19.025,8.89) 12(-19.025,8.255) 13(-19.025,7.62) 14(-19.025,6.985) 15(-19.025,6.35) 16(-19.025,5.715) 17(-19.025,5.08) 18(-19.025,4.445) 19(-19.025,3.81) 20(-19.025,3.175) 21(-19.025,2.54) 22(-19.025,1.905) 23(-19.025,1.27) 24(-19.025,0.635) 25(-19.025,0) 26(-19.025,-0.635) 27(-19.025,-1.27) 28(-19.025,-1.905) 29(-19.025,-2.54) 30(-19.025,-3.175) 31(-19.025,-3.81) 32(-19.025,-4.445) 33(-19.025,-5.08) 34(-19.025,-5.715) 35(-19.025,-6.35) 36(-19.025,-6.985) 37(-19.025,-7.62) 38(-19.025,-8.255) 39(-19.025,-8.89) 40(-19.025,-9.525) 41(-19.025,-10.16) 42(-19.025,-10.795) 43(-19.025,-11.43) 44(-19.025,-12.065) 45(-19.025,-12.7) 46(-19.025,-13.335) 47(-19.025,-13.97) 48(-19.025,-14.605) 49(-19.025,-15.24) 99(19.025,-15.24) 100(19.025,-14.605) 101(19.025,-13.97) 102(19.025,-13.335) 103(19.025,-12.7) 104(19.025,-12.065) 105(19.025,-11.43) 106(19.025,-10.795) 107(19.025,-10.16) 108(19.025,-9.525) 109(19.025,-8.89) 110(19.025,-8.255) 111(19.025,-7.62) 112(19.025,-6.985) 113(19.025,-6.35) 114(19.025,-5.715) 115(19.025,-5.08) 116(19.025,-4.445) 117(19.025,-3.81) 118(19.025,-3.175) 119(19.025,-2.54) 120(19.025,-1.905) 121(19.025,-1.27) 122(19.025,-0.635) 123(19.025,0) 124(19.025,0.635) 125(19.025,1.27) 126(19.025,1.905) 127(19.025,2.54) 128(19.025,3.175) 129(19.025,3.81) 130(19.025,4.445) 131(19.025,5.08) 132(19.025,5.715) 133(19.025,6.35) 134(19.025,6.985) 135(19.025,7.62) 136(19.025,8.255) 137(19.025,8.89) 138(19.025,9.525) 139(19.025,10.16) 140(19.025,10.795) 141(19.025,11.43) 142(19.025,12.065) 143(19.025,12.7) 144(19.025,13.335) 145(19.025,13.97) 146(19.025,14.605) 147(19.025,15.24)
  rect 0.35x2.65 smd: 50(-15.24,-19.025) 51(-14.605,-19.025) 52(-13.97,-19.025) 53(-13.335,-19.025) 54(-12.7,-19.025) 55(-12.065,-19.025) 56(-11.43,-19.025) 57(-10.795,-19.025) 58(-10.16,-19.025) 59(-9.525,-19.025) 60(-8.89,-19.025) 61(-8.255,-19.025) 62(-7.62,-19.025) 63(-6.985,-19.025) 64(-6.35,-19.025) 65(-5.715,-19.025) 66(-5.08,-19.025) 67(-4.445,-19.025) 68(-3.81,-19.025) 69(-3.175,-19.025) 70(-2.54,-19.025) 71(-1.905,-19.025) 72(-1.27,-19.025) 73(-0.635,-19.025) 74(0,-19.025) 75(0.635,-19.025) 76(1.27,-19.025) 77(1.905,-19.025) 78(2.54,-19.025) 79(3.175,-19.025) 80(3.81,-19.025) 81(4.445,-19.025) 82(5.08,-19.025) 83(5.715,-19.025) 84(6.35,-19.025) 85(6.985,-19.025) 86(7.62,-19.025) 87(8.255,-19.025) 88(8.89,-19.025) 89(9.525,-19.025) 90(10.16,-19.025) 91(10.795,-19.025) 92(11.43,-19.025) 93(12.065,-19.025) 94(12.7,-19.025) 95(13.335,-19.025) 96(13.97,-19.025) 97(14.605,-19.025) 98(15.24,-19.025) 148(15.24,19.025) 149(14.605,19.025) 150(13.97,19.025) 151(13.335,19.025) 152(12.7,19.025) 153(12.065,19.025) 154(11.43,19.025) 155(10.795,19.025) 156(10.16,19.025) 157(9.525,19.025) 158(8.89,19.025) 159(8.255,19.025) 160(7.62,19.025) 161(6.985,19.025) 162(6.35,19.025) 163(5.715,19.025) 164(5.08,19.025) 165(4.445,19.025) 166(3.81,19.025) 167(3.175,19.025) 168(2.54,19.025) 169(1.905,19.025) 170(1.27,19.025) 171(0.635,19.025) 172(0,19.025) 173(-0.635,19.025) 174(-1.27,19.025) 175(-1.905,19.025) 176(-2.54,19.025) 177(-3.175,19.025) 178(-3.81,19.025) 179(-4.445,19.025) 180(-5.08,19.025) 181(-5.715,19.025) 182(-6.35,19.025) 183(-6.985,19.025) 184(-7.62,19.025) 185(-8.255,19.025) 186(-8.89,19.025) 187(-9.525,19.025) 188(-10.16,19.025) 189(-10.795,19.025) 190(-11.43,19.025) 191(-12.065,19.025) 192(-12.7,19.025) 193(-13.335,19.025) 194(-13.97,19.025) 195(-14.605,19.025) 196(-15.24,19.025)
Top Overlay:
  circle w0.25: c-19.025,15.965 r0.125
  lines w0.2: -17.3,-17.3 -17.3,17.3 17.3,17.3 17.3,-17.3 -17.3,-17.3

## CQFP-G196/Z40.6 [mm]
pads (196):
  rect 2.65x0.4 smd: 1(-18.975,15.24) 2(-18.975,14.605) 3(-18.975,13.97) 4(-18.975,13.335) 5(-18.975,12.7) 6(-18.975,12.065) 7(-18.975,11.43) 8(-18.975,10.795) 9(-18.975,10.16) 10(-18.975,9.525) 11(-18.975,8.89) 12(-18.975,8.255) 13(-18.975,7.62) 14(-18.975,6.985) 15(-18.975,6.35) 16(-18.975,5.715) 17(-18.975,5.08) 18(-18.975,4.445) 19(-18.975,3.81) 20(-18.975,3.175) 21(-18.975,2.54) 22(-18.975,1.905) 23(-18.975,1.27) 24(-18.975,0.635) 25(-18.975,0) 26(-18.975,-0.635) 27(-18.975,-1.27) 28(-18.975,-1.905) 29(-18.975,-2.54) 30(-18.975,-3.175) 31(-18.975,-3.81) 32(-18.975,-4.445) 33(-18.975,-5.08) 34(-18.975,-5.715) 35(-18.975,-6.35) 36(-18.975,-6.985) 37(-18.975,-7.62) 38(-18.975,-8.255) 39(-18.975,-8.89) 40(-18.975,-9.525) 41(-18.975,-10.16) 42(-18.975,-10.795) 43(-18.975,-11.43) 44(-18.975,-12.065) 45(-18.975,-12.7) 46(-18.975,-13.335) 47(-18.975,-13.97) 48(-18.975,-14.605) 49(-18.975,-15.24) 99(18.975,-15.24) 100(18.975,-14.605) 101(18.975,-13.97) 102(18.975,-13.335) 103(18.975,-12.7) 104(18.975,-12.065) 105(18.975,-11.43) 106(18.975,-10.795) 107(18.975,-10.16) 108(18.975,-9.525) 109(18.975,-8.89) 110(18.975,-8.255) 111(18.975,-7.62) 112(18.975,-6.985) 113(18.975,-6.35) 114(18.975,-5.715) 115(18.975,-5.08) 116(18.975,-4.445) 117(18.975,-3.81) 118(18.975,-3.175) 119(18.975,-2.54) 120(18.975,-1.905) 121(18.975,-1.27) 122(18.975,-0.635) 123(18.975,0) 124(18.975,0.635) 125(18.975,1.27) 126(18.975,1.905) 127(18.975,2.54) 128(18.975,3.175) 129(18.975,3.81) 130(18.975,4.445) 131(18.975,5.08) 132(18.975,5.715) 133(18.975,6.35) 134(18.975,6.985) 135(18.975,7.62) 136(18.975,8.255) 137(18.975,8.89) 138(18.975,9.525) 139(18.975,10.16) 140(18.975,10.795) 141(18.975,11.43) 142(18.975,12.065) 143(18.975,12.7) 144(18.975,13.335) 145(18.975,13.97) 146(18.975,14.605) 147(18.975,15.24)
  rect 0.4x2.65 smd: 50(-15.24,-18.975) 51(-14.605,-18.975) 52(-13.97,-18.975) 53(-13.335,-18.975) 54(-12.7,-18.975) 55(-12.065,-18.975) 56(-11.43,-18.975) 57(-10.795,-18.975) 58(-10.16,-18.975) 59(-9.525,-18.975) 60(-8.89,-18.975) 61(-8.255,-18.975) 62(-7.62,-18.975) 63(-6.985,-18.975) 64(-6.35,-18.975) 65(-5.715,-18.975) 66(-5.08,-18.975) 67(-4.445,-18.975) 68(-3.81,-18.975) 69(-3.175,-18.975) 70(-2.54,-18.975) 71(-1.905,-18.975) 72(-1.27,-18.975) 73(-0.635,-18.975) 74(0,-18.975) 75(0.635,-18.975) 76(1.27,-18.975) 77(1.905,-18.975) 78(2.54,-18.975) 79(3.175,-18.975) 80(3.81,-18.975) 81(4.445,-18.975) 82(5.08,-18.975) 83(5.715,-18.975) 84(6.35,-18.975) 85(6.985,-18.975) 86(7.62,-18.975) 87(8.255,-18.975) 88(8.89,-18.975) 89(9.525,-18.975) 90(10.16,-18.975) 91(10.795,-18.975) 92(11.43,-18.975) 93(12.065,-18.975) 94(12.7,-18.975) 95(13.335,-18.975) 96(13.97,-18.975) 97(14.605,-18.975) 98(15.24,-18.975) 148(15.24,18.975) 149(14.605,18.975) 150(13.97,18.975) 151(13.335,18.975) 152(12.7,18.975) 153(12.065,18.975) 154(11.43,18.975) 155(10.795,18.975) 156(10.16,18.975) 157(9.525,18.975) 158(8.89,18.975) 159(8.255,18.975) 160(7.62,18.975) 161(6.985,18.975) 162(6.35,18.975) 163(5.715,18.975) 164(5.08,18.975) 165(4.445,18.975) 166(3.81,18.975) 167(3.175,18.975) 168(2.54,18.975) 169(1.905,18.975) 170(1.27,18.975) 171(0.635,18.975) 172(0,18.975) 173(-0.635,18.975) 174(-1.27,18.975) 175(-1.905,18.975) 176(-2.54,18.975) 177(-3.175,18.975) 178(-3.81,18.975) 179(-4.445,18.975) 180(-5.08,18.975) 181(-5.715,18.975) 182(-6.35,18.975) 183(-6.985,18.975) 184(-7.62,18.975) 185(-8.255,18.975) 186(-8.89,18.975) 187(-9.525,18.975) 188(-10.16,18.975) 189(-10.795,18.975) 190(-11.43,18.975) 191(-12.065,18.975) 192(-12.7,18.975) 193(-13.335,18.975) 194(-13.97,18.975) 195(-14.605,18.975) 196(-15.24,18.975)
Top Overlay:
  circle w0.25: c-18.975,15.99 r0.125
  lines w0.2: -17.25,-17.25 17.25,-17.25 17.25,17.25 -17.25,17.25 -17.25,-17.25

## CQFP-G256 [mm]
pads (256):
  rect 2.65x0.25 smd: 1(-19.875,15.75) 2(-19.875,15.25) 3(-19.875,14.75) 4(-19.875,14.25) 5(-19.875,13.75) 6(-19.875,13.25) 7(-19.875,12.75) 8(-19.875,12.25) 9(-19.875,11.75) 10(-19.875,11.25) 11(-19.875,10.75) 12(-19.875,10.25) 13(-19.875,9.75) 14(-19.875,9.25) 15(-19.875,8.75) 16(-19.875,8.25) 17(-19.875,7.75) 18(-19.875,7.25) 19(-19.875,6.75) 20(-19.875,6.25) 21(-19.875,5.75) 22(-19.875,5.25) 23(-19.875,4.75) 24(-19.875,4.25) 25(-19.875,3.75) 26(-19.875,3.25) 27(-19.875,2.75) 28(-19.875,2.25) 29(-19.875,1.75) 30(-19.875,1.25) 31(-19.875,0.75) 32(-19.875,0.25) 33(-19.875,-0.25) 34(-19.875,-0.75) 35(-19.875,-1.25) 36(-19.875,-1.75) 37(-19.875,-2.25) 38(-19.875,-2.75) 39(-19.875,-3.25) 40(-19.875,-3.75) 41(-19.875,-4.25) 42(-19.875,-4.75) 43(-19.875,-5.25) 44(-19.875,-5.75) 45(-19.875,-6.25) 46(-19.875,-6.75) 47(-19.875,-7.25) 48(-19.875,-7.75) 49(-19.875,-8.25) 50(-19.875,-8.75) 51(-19.875,-9.25) 52(-19.875,-9.75) 53(-19.875,-10.25) 54(-19.875,-10.75) 55(-19.875,-11.25) 56(-19.875,-11.75) 57(-19.875,-12.25) 58(-19.875,-12.75) 59(-19.875,-13.25) 60(-19.875,-13.75) 61(-19.875,-14.25) 62(-19.875,-14.75) 63(-19.875,-15.25) 64(-19.875,-15.75) 129(19.875,-15.75) 130(19.875,-15.25) 131(19.875,-14.75) 132(19.875,-14.25) 133(19.875,-13.75) 134(19.875,-13.25) 135(19.875,-12.75) 136(19.875,-12.25) 137(19.875,-11.75) 138(19.875,-11.25) 139(19.875,-10.75) 140(19.875,-10.25) 141(19.875,-9.75) 142(19.875,-9.25) 143(19.875,-8.75) 144(19.875,-8.25) 145(19.875,-7.75) 146(19.875,-7.25) 147(19.875,-6.75) 148(19.875,-6.25) 149(19.875,-5.75) 150(19.875,-5.25) 151(19.875,-4.75) 152(19.875,-4.25) 153(19.875,-3.75) 154(19.875,-3.25) 155(19.875,-2.75) 156(19.875,-2.25) 157(19.875,-1.75) 158(19.875,-1.25) 159(19.875,-0.75) 160(19.875,-0.25) 161(19.875,0.25) 162(19.875,0.75) 163(19.875,1.25) 164(19.875,1.75) 165(19.875,2.25) 166(19.875,2.75) 167(19.875,3.25) 168(19.875,3.75) 169(19.875,4.25) 170(19.875,4.75) 171(19.875,5.25) 172(19.875,5.75) 173(19.875,6.25) 174(19.875,6.75) 175(19.875,7.25) 176(19.875,7.75) 177(19.875,8.25) 178(19.875,8.75) 179(19.875,9.25) 180(19.875,9.75) 181(19.875,10.25) 182(19.875,10.75) 183(19.875,11.25) 184(19.875,11.75) 185(19.875,12.25) 186(19.875,12.75) 187(19.875,13.25) 188(19.875,13.75) 189(19.875,14.25) 190(19.875,14.75) 191(19.875,15.25) 192(19.875,15.75)
  rect 0.25x2.65 smd: 65(-15.75,-19.875) 66(-15.25,-19.875) 67(-14.75,-19.875) 68(-14.25,-19.875) 69(-13.75,-19.875) 70(-13.25,-19.875) 71(-12.75,-19.875) 72(-12.25,-19.875) 73(-11.75,-19.875) 74(-11.25,-19.875) 75(-10.75,-19.875) 76(-10.25,-19.875) 77(-9.75,-19.875) 78(-9.25,-19.875) 79(-8.75,-19.875) 80(-8.25,-19.875) 81(-7.75,-19.875) 82(-7.25,-19.875) 83(-6.75,-19.875) 84(-6.25,-19.875) 85(-5.75,-19.875) 86(-5.25,-19.875) 87(-4.75,-19.875) 88(-4.25,-19.875) 89(-3.75,-19.875) 90(-3.25,-19.875) 91(-2.75,-19.875) 92(-2.25,-19.875) 93(-1.75,-19.875) 94(-1.25,-19.875) 95(-0.75,-19.875) 96(-0.25,-19.875) 97(0.25,-19.875) 98(0.75,-19.875) 99(1.25,-19.875) 100(1.75,-19.875) 101(2.25,-19.875) 102(2.75,-19.875) 103(3.25,-19.875) 104(3.75,-19.875) 105(4.25,-19.875) 106(4.75,-19.875) 107(5.25,-19.875) 108(5.75,-19.875) 109(6.25,-19.875) 110(6.75,-19.875) 111(7.25,-19.875) 112(7.75,-19.875) 113(8.25,-19.875) 114(8.75,-19.875) 115(9.25,-19.875) 116(9.75,-19.875) 117(10.25,-19.875) 118(10.75,-19.875) 119(11.25,-19.875) 120(11.75,-19.875) 121(12.25,-19.875) 122(12.75,-19.875) 123(13.25,-19.875) 124(13.75,-19.875) 125(14.25,-19.875) 126(14.75,-19.875) 127(15.25,-19.875) 128(15.75,-19.875) 193(15.75,19.875) 194(15.25,19.875) 195(14.75,19.875) 196(14.25,19.875) 197(13.75,19.875) 198(13.25,19.875) 199(12.75,19.875) 200(12.25,19.875) 201(11.75,19.875) 202(11.25,19.875) 203(10.75,19.875) 204(10.25,19.875) 205(9.75,19.875) 206(9.25,19.875) 207(8.75,19.875) 208(8.25,19.875) 209(7.75,19.875) 210(7.25,19.875) 211(6.75,19.875) 212(6.25,19.875) 213(5.75,19.875) 214(5.25,19.875) 215(4.75,19.875) 216(4.25,19.875) 217(3.75,19.875) 218(3.25,19.875) 219(2.75,19.875) 220(2.25,19.875) 221(1.75,19.875) 222(1.25,19.875) 223(0.75,19.875) 224(0.25,19.875) 225(-0.25,19.875) 226(-0.75,19.875) 227(-1.25,19.875) 228(-1.75,19.875) 229(-2.25,19.875) 230(-2.75,19.875) 231(-3.25,19.875) 232(-3.75,19.875) 233(-4.25,19.875) 234(-4.75,19.875) 235(-5.25,19.875) 236(-5.75,19.875) 237(-6.25,19.875) 238(-6.75,19.875) 239(-7.25,19.875) 240(-7.75,19.875) 241(-8.25,19.875) 242(-8.75,19.875) 243(-9.25,19.875) 244(-9.75,19.875) 245(-10.25,19.875) 246(-10.75,19.875) 247(-11.25,19.875) 248(-11.75,19.875) 249(-12.25,19.875) 250(-12.75,19.875) 251(-13.25,19.875) 252(-13.75,19.875) 253(-14.25,19.875) 254(-14.75,19.875) 255(-15.25,19.875) 256(-15.75,19.875)
Top Overlay:
  circle w0.25: c-19.875,16.425 r0.125
  lines w0.2: -18.15,-18.15 -18.15,18.15 18.15,18.15 18.15,-18.15 -18.15,-18.15

## CQFP-G308 [mm]
pads (308):
  rect 2.65x0.35 smd: 1(-27.925,24.13) 2(-27.925,23.495) 3(-27.925,22.86) 4(-27.925,22.225) 5(-27.925,21.59) 6(-27.925,20.955) 7(-27.925,20.32) 8(-27.925,19.685) 9(-27.925,19.05) 10(-27.925,18.415) 11(-27.925,17.78) 12(-27.925,17.145) 13(-27.925,16.51) 14(-27.925,15.875) 15(-27.925,15.24) 16(-27.925,14.605) 17(-27.925,13.97) 18(-27.925,13.335) 19(-27.925,12.7) 20(-27.925,12.065) 21(-27.925,11.43) 22(-27.925,10.795) 23(-27.925,10.16) 24(-27.925,9.525) 25(-27.925,8.89) 26(-27.925,8.255) 27(-27.925,7.62) 28(-27.925,6.985) 29(-27.925,6.35) 30(-27.925,5.715) 31(-27.925,5.08) 32(-27.925,4.445) 33(-27.925,3.81) 34(-27.925,3.175) 35(-27.925,2.54) 36(-27.925,1.905) 37(-27.925,1.27) 38(-27.925,0.635) 39(-27.925,0) 40(-27.925,-0.635) 41(-27.925,-1.27) 42(-27.925,-1.905) 43(-27.925,-2.54) 44(-27.925,-3.175) 45(-27.925,-3.81) 46(-27.925,-4.445) 47(-27.925,-5.08) 48(-27.925,-5.715) 49(-27.925,-6.35) 50(-27.925,-6.985) 51(-27.925,-7.62) 52(-27.925,-8.255) 53(-27.925,-8.89) 54(-27.925,-9.525) 55(-27.925,-10.16) 56(-27.925,-10.795) 57(-27.925,-11.43) 58(-27.925,-12.065) 59(-27.925,-12.7) 60(-27.925,-13.335) 61(-27.925,-13.97) 62(-27.925,-14.605) 63(-27.925,-15.24) 64(-27.925,-15.875) 65(-27.925,-16.51) 66(-27.925,-17.145) 67(-27.925,-17.78) 68(-27.925,-18.415) 69(-27.925,-19.05) 70(-27.925,-19.685) 71(-27.925,-20.32) 72(-27.925,-20.955) 73(-27.925,-21.59) 74(-27.925,-22.225) 75(-27.925,-22.86) 76(-27.925,-23.495) 77(-27.925,-24.13) 155(27.925,-24.13) 156(27.925,-23.495) 157(27.925,-22.86) 158(27.925,-22.225) 159(27.925,-21.59) 160(27.925,-20.955) 161(27.925,-20.32) 162(27.925,-19.685) 163(27.925,-19.05) 164(27.925,-18.415) 165(27.925,-17.78) 166(27.925,-17.145) 167(27.925,-16.51) 168(27.925,-15.875) 169(27.925,-15.24) 170(27.925,-14.605) 171(27.925,-13.97) 172(27.925,-13.335) 173(27.925,-12.7) 174(27.925,-12.065) 175(27.925,-11.43) 176(27.925,-10.795) 177(27.925,-10.16) 178(27.925,-9.525) 179(27.925,-8.89) 180(27.925,-8.255) 181(27.925,-7.62) 182(27.925,-6.985) 183(27.925,-6.35) 184(27.925,-5.715) 185(27.925,-5.08) 186(27.925,-4.445) 187(27.925,-3.81) 188(27.925,-3.175) 189(27.925,-2.54) 190(27.925,-1.905) 191(27.925,-1.27) 192(27.925,-0.635) 193(27.925,0) 194(27.925,0.635) 195(27.925,1.27) 196(27.925,1.905) 197(27.925,2.54) 198(27.925,3.175) 199(27.925,3.81) 200(27.925,4.445) 201(27.925,5.08) 202(27.925,5.715) 203(27.925,6.35) 204(27.925,6.985) 205(27.925,7.62) 206(27.925,8.255) 207(27.925,8.89) 208(27.925,9.525) 209(27.925,10.16) 210(27.925,10.795) 211(27.925,11.43) 212(27.925,12.065) 213(27.925,12.7) 214(27.925,13.335) 215(27.925,13.97) 216(27.925,14.605) 217(27.925,15.24) 218(27.925,15.875) 219(27.925,16.51) 220(27.925,17.145) 221(27.925,17.78) 222(27.925,18.415) 223(27.925,19.05) 224(27.925,19.685) 225(27.925,20.32) 226(27.925,20.955) 227(27.925,21.59) 228(27.925,22.225) 229(27.925,22.86) 230(27.925,23.495) 231(27.925,24.13)
  rect 0.35x2.65 smd: 78(-24.13,-27.925) 79(-23.495,-27.925) 80(-22.86,-27.925) 81(-22.225,-27.925) 82(-21.59,-27.925) 83(-20.955,-27.925) 84(-20.32,-27.925) 85(-19.685,-27.925) 86(-19.05,-27.925) 87(-18.415,-27.925) 88(-17.78,-27.925) 89(-17.145,-27.925) 90(-16.51,-27.925) 91(-15.875,-27.925) 92(-15.24,-27.925) 93(-14.605,-27.925) 94(-13.97,-27.925) 95(-13.335,-27.925) 96(-12.7,-27.925) 97(-12.065,-27.925) 98(-11.43,-27.925) 99(-10.795,-27.925) 100(-10.16,-27.925) 101(-9.525,-27.925) 102(-8.89,-27.925) 103(-8.255,-27.925) 104(-7.62,-27.925) 105(-6.985,-27.925) 106(-6.35,-27.925) 107(-5.715,-27.925) 108(-5.08,-27.925) 109(-4.445,-27.925) 110(-3.81,-27.925) 111(-3.175,-27.925) 112(-2.54,-27.925) 113(-1.905,-27.925) 114(-1.27,-27.925) 115(-0.635,-27.925) 116(0,-27.925) 117(0.635,-27.925) 118(1.27,-27.925) 119(1.905,-27.925) 120(2.54,-27.925) 121(3.175,-27.925) 122(3.81,-27.925) 123(4.445,-27.925) 124(5.08,-27.925) 125(5.715,-27.925) 126(6.35,-27.925) 127(6.985,-27.925) 128(7.62,-27.925) 129(8.255,-27.925) 130(8.89,-27.925) 131(9.525,-27.925) 132(10.16,-27.925) 133(10.795,-27.925) 134(11.43,-27.925) 135(12.065,-27.925) 136(12.7,-27.925) 137(13.335,-27.925) 138(13.97,-27.925) 139(14.605,-27.925) 140(15.24,-27.925) 141(15.875,-27.925) 142(16.51,-27.925) 143(17.145,-27.925) 144(17.78,-27.925) 145(18.415,-27.925) 146(19.05,-27.925) 147(19.685,-27.925) 148(20.32,-27.925) 149(20.955,-27.925) 150(21.59,-27.925) 151(22.225,-27.925) 152(22.86,-27.925) 153(23.495,-27.925) 154(24.13,-27.925) 232(24.13,27.925) 233(23.495,27.925) 234(22.86,27.925) 235(22.225,27.925) 236(21.59,27.925) 237(20.955,27.925) 238(20.32,27.925) 239(19.685,27.925) 240(19.05,27.925) 241(18.415,27.925) 242(17.78,27.925) 243(17.145,27.925) 244(16.51,27.925) 245(15.875,27.925) 246(15.24,27.925) 247(14.605,27.925) 248(13.97,27.925) 249(13.335,27.925) 250(12.7,27.925) 251(12.065,27.925) 252(11.43,27.925) 253(10.795,27.925) 254(10.16,27.925) 255(9.525,27.925) 256(8.89,27.925) 257(8.255,27.925) 258(7.62,27.925) 259(6.985,27.925) 260(6.35,27.925) 261(5.715,27.925) 262(5.08,27.925) 263(4.445,27.925) 264(3.81,27.925) 265(3.175,27.925) 266(2.54,27.925) 267(1.905,27.925) 268(1.27,27.925) 269(0.635,27.925) 270(0,27.925) 271(-0.635,27.925) 272(-1.27,27.925) 273(-1.905,27.925) 274(-2.54,27.925) 275(-3.175,27.925) 276(-3.81,27.925) 277(-4.445,27.925) 278(-5.08,27.925) 279(-5.715,27.925) 280(-6.35,27.925) 281(-6.985,27.925) 282(-7.62,27.925) 283(-8.255,27.925) 284(-8.89,27.925) 285(-9.525,27.925) 286(-10.16,27.925) 287(-10.795,27.925) 288(-11.43,27.925) 289(-12.065,27.925) 290(-12.7,27.925) 291(-13.335,27.925) 292(-13.97,27.925) 293(-14.605,27.925) 294(-15.24,27.925) 295(-15.875,27.925) 296(-16.51,27.925) 297(-17.145,27.925) 298(-17.78,27.925) 299(-18.415,27.925) 300(-19.05,27.925) 301(-19.685,27.925) 302(-20.32,27.925) 303(-20.955,27.925) 304(-21.59,27.925) 305(-22.225,27.925) 306(-22.86,27.925) 307(-23.495,27.925) 308(-24.13,27.925)
Top Overlay:
  circle w0.25: c-27.925,24.855 r0.125
  lines w0.2: -26.2,-26.2 -26.2,26.2 26.2,26.2 26.2,-26.2 -26.2,-26.2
